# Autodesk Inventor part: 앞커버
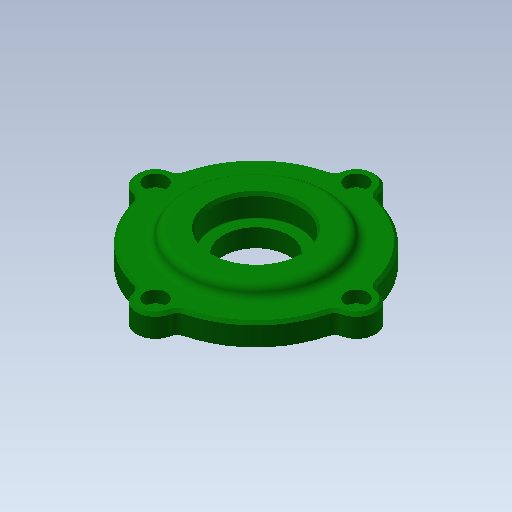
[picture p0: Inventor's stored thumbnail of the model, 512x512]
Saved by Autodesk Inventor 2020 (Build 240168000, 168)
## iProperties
Created: 2015-12
Part Number: 앞커버
Document SubType Name: Modeling
Designer: mdu
Density: 1 g/cm^3
Material: 알루미늄 6061
Appearance: 진녹색
Company: 한국ATC센터
Author: mdu
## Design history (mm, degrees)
sketch "스케치1"
  geometry: C1 r 1.621 at (0, 6.75) reference; C2 r 1.621 at (-37, -30.25) reference; C3 r 1.621 at (0, -67.25) reference; C4 r 1.621 at (37, -30.25) reference; C5 r 10 at (0, -30.25) reference; C6 r 12 at (0, -30.25); C7 r 24.5 at (0, -30.25) reference; A1 r 3 centre (-38.77, -20.408) between (-38.239, -23.361) and (-35.862, -21.146) reference; A2 r 7 centre (-37, -30.25) between (-38.239, -23.361) and (-38.239, -37.139) reference; A3 r 3 centre (-38.77, -40.092) between (-35.862, -39.354) and (-38.239, -37.139) reference; A4 r 37 centre (0, -30.25) between (-35.862, -39.354) and (-9.104, -66.113) reference; A5 r 3 centre (-9.842, -69.02) between (-6.889, -68.489) and (-9.104, -66.113) reference; A6 r 7 centre (0, -67.25) between (-6.889, -68.489) and (6.889, -68.489) reference; A7 r 3 centre (9.842, -69.02) between (9.104, -66.112) and (6.889, -68.489) reference; A8 r 37 centre (0, -30.25) between (9.104, -66.112) and (35.863, -39.354) reference; A9 r 3 centre (38.77, -40.092) between (38.239, -37.139) and (35.863, -39.354) reference; A10 r 7 centre (37, -30.25) between (38.239, -37.139) and (38.239, -23.361) reference; A11 r 3 centre (38.77, -20.408) between (35.863, -21.146) and (38.239, -23.361) reference; A12 r 37 centre (0, -30.25) between (35.863, -21.146) and (9.104, 5.612) reference; A13 r 3 centre (9.842, 8.52) between (6.889, 7.989) and (9.104, 5.612) reference; A14 r 7 centre (0, 6.75) between (6.889, 7.989) and (-6.889, 7.989) reference; A15 r 3 centre (-9.842, 8.52) between (-9.104, 5.612) and (-6.889, 7.989) reference; A16 r 37 centre (0, -30.25) between (-9.104, 5.612) and (-35.862, -21.146) reference; 1 further point
  constraints: 1 centre point, 1 coincident
  dimensions: "d2" = 2 radial gap between concentric circles of C6 C5
extrude "돌출1" new body sketch "스케치1" distance "d0" = 8; taper "d1" = 0 deg
sketch "스케치2"
  geometry: C1 r 23.5 at (0, -30.25) reference; C2 r 12 at (0, -30.25) reference; 1 further point
extrude "돌출2" join sketch "스케치2" distance "d4" = 6; taper "d5" = 0 deg
sketch "스케치9"
  geometry: C1 r 21 at (0, 0); C2 r 23.5 at (0, 0) reference; 1 further point
  constraints: 1 centre point, 1 coincident
  dimensions: "d60" = 42 diameter of C1
extrude "돌출6" cut sketch "스케치9" distance "d63" = 3; taper "d64" = 0 deg
node "작업 평면1"
sketch "스케치4"
  geometry: C1 r 12 at (0, -30.25) reference; C2 r 27 at (0, -30.25); 1 further point
  constraints: 1 centre point
  dimensions: "d10" = 15 radial gap between concentric circles of C1 C2
extrude "돌출4" join sketch "스케치4" distance "d11" = 4; taper "d12" = -20 deg
fillet "모깎기2" dims "d13" = 3
node "작업점1"
  node "작업축1"
chamfer "모따기2" distance "d24" = 1; stored, may be unused: second distance "d25" = 2, angle "d26" = 45 deg
hole "구멍6" diameter "d43" = 4.5; stored, may be unused: countersink angle "d47" = 90 deg, drill point angle "d49" = 118 deg; dims "d41" = 10, "d42" = 10, "d44" = 6, "d45" = 8, "d46" = 4.4, "d48" = 8
sketch "스케치8"
  geometry: C1 r 13.456 at (0, 0) reference; C2 r 16 at (0, 0); 1 further point
  constraints: 1 centre point, 1 coincident
  dimensions: "d53" = 32 diameter of C2
extrude "돌출5" cut sketch "스케치8" distance "d54" = 8.3; taper "d55" = 0 deg
fillet "모깎기3" dims "d56" = 0.3
chamfer "모따기3" distance "d57" = 1.2; stored, may be unused: second distance "d58" = 2, angle "d59" = 30 deg
node "솔리드1"
pattern_circular "원형 패턴1" dims angle "d51" = 360 deg
node "참조1"
node "참조2"
